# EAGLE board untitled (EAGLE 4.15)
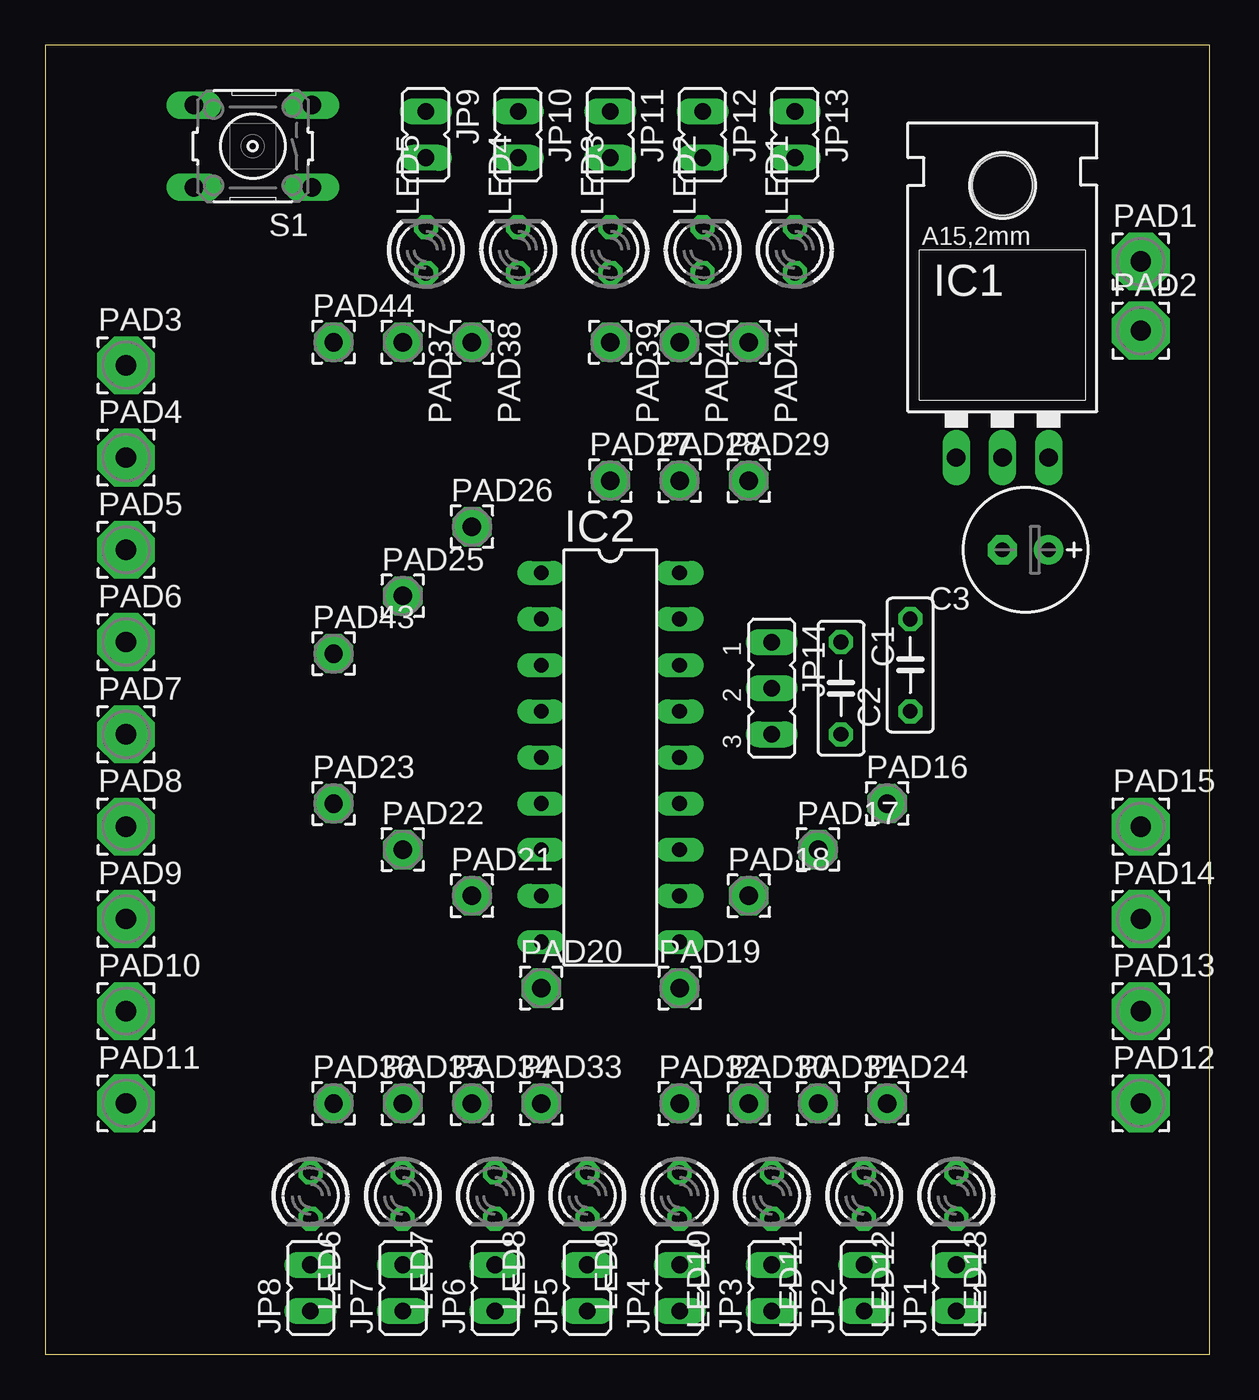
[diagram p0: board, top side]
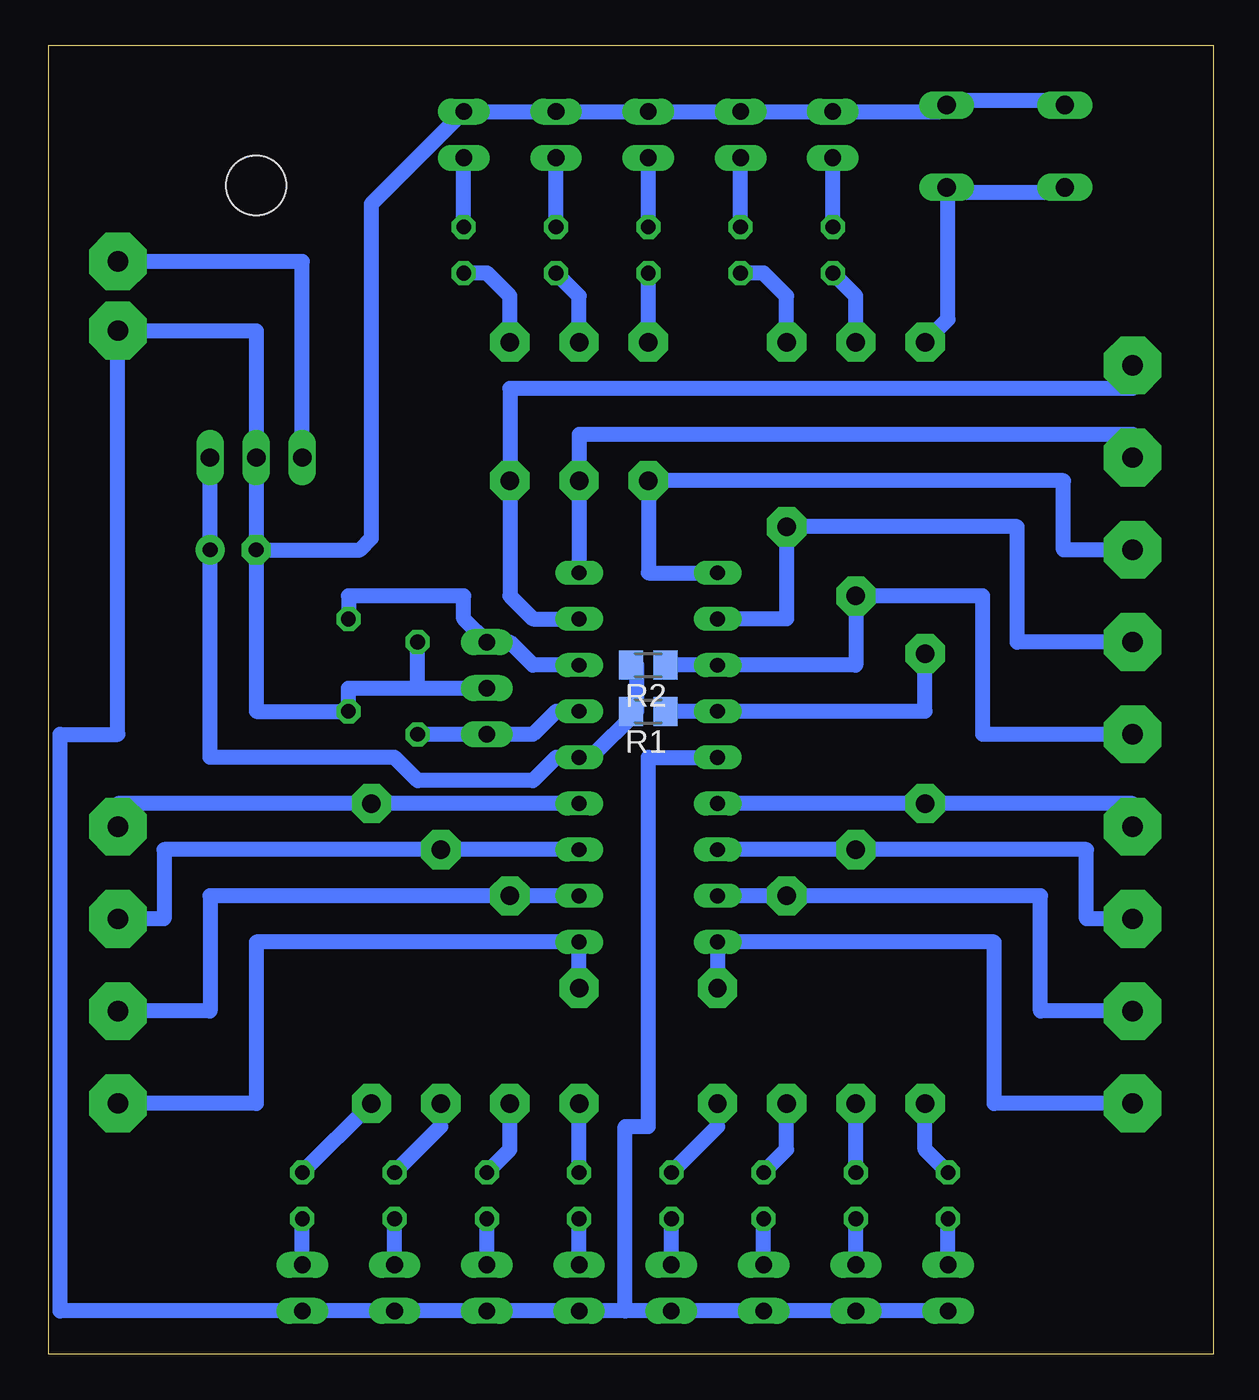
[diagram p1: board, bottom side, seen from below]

Size 64.11 x 72.06 mm. Coordinates in mm from the lower left corner, seen from the top.
Outline: 0,0 64.11,0 64.11,72.06 0,72.06 0,0
Copper layers (1*16): Top 0.035mm / dielectric 1.5mm / Bottom 0.035mm
Design rules "default": minimum track width 10mil, minimum drill 24mil, track to track 8mil, track to pad 8mil, pad to pad 8mil, via to via 8mil, smd to smd 8mil, copper to edge 40mil, drill to drill 8mil, minimum pad ring 10mil, minimum via ring 8mil, stop-mask expansion 4mil, vias tented up to drill 0mil, thermal gap 10mil

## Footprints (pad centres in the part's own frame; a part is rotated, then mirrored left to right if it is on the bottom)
C050-025X075 = drill 0.813 octagon: 1 -2.54,0; 2 2.54,0
E2,5-7 = drill 0.813 pad 1.6 round: + -1.27,0 | drill 0.813 pad 1.6 octagon: - 1.27,0
78XXL = drill 1.016 long: GND 0,-3.81; IN -2.54,-3.81; OUT 2.54,-3.81 | hole 3.302: 0,11.176
DIL18 = drill 0.813 long: 1 -10.16,-3.81; 2 -7.62,-3.81; 3 -5.08,-3.81; 4 -2.54,-3.81; 5 0,-3.81; 6 2.54,-3.81; 7 5.08,-3.81; 8 7.62,-3.81; 9 10.16,-3.81; 10 10.16,3.81; 11 7.62,3.81; 12 5.08,3.81; 13 2.54,3.81; 14 0,3.81; 15 -2.54,3.81; 16 -5.08,3.81; 17 -7.62,3.81; 18 -10.16,3.81
JP1 = drill 0.914 long: 1 0,-1.27; 2 0,1.27
JP2 = drill 0.914 long: 1 -2.54,0; 2 0,0; 3 2.54,0
LED3MM = drill 0.813 octagon: A -1.27,0; K 1.27,0
3,17/1,1 = drill 1.118 pad 3.175 octagon: 1 0,0
2,15/1,0 = drill 1.016 pad 2.159 octagon: 1 0,0
M0805 = smd 1.3 x 1.6: 1 -0.95,0; 2 0.95,0
B3F-10XX = drill 1.016 long: 1 -3.251,2.261; 2 3.251,2.261; 3 -3.251,-2.261; 4 3.251,-2.261

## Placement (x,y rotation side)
C1  [C050-025X075]  43.81,36.66 270 top
C2  [C050-025X075]  47.62,37.94 90 top
C3  [E2,5-7]  53.97,44.28 180 top
IC1  [78XXL]  52.7,53.17 0 top
IC2  PIC16F84AP  [DIL18]  31.11,32.85 270 top
JP1  [JP1]  50.16,3.64 0 top
JP2  [JP1]  45.08,3.64 0 top
JP3  [JP1]  40,3.64 0 top
JP4  [JP1]  34.92,3.64 0 top
JP5  [JP1]  29.84,3.64 0 top
JP6  [JP1]  24.76,3.64 0 top
JP7  [JP1]  19.68,3.64 0 top
JP8  [JP1]  14.6,3.64 0 top
JP9  [JP1]  20.95,67.14 180 top
JP10  [JP1]  26.03,67.14 180 top
JP11  [JP1]  31.11,67.14 180 top
JP12  [JP1]  36.19,67.14 180 top
JP13  [JP1]  41.27,67.14 180 top
JP14  [JP2]  40,36.66 270 top
LED1  [LED3MM]  41.27,60.8 90 top
LED2  [LED3MM]  36.19,60.8 90 top
LED3  [LED3MM]  31.11,60.8 90 top
LED4  [LED3MM]  26.03,60.8 90 top
LED5  [LED3MM]  20.95,60.8 90 top
LED6  [LED3MM]  14.6,8.73 270 top
LED7  [LED3MM]  19.68,8.73 270 top
LED8  [LED3MM]  24.76,8.73 270 top
LED9  [LED3MM]  29.84,8.73 270 top
LED10  [LED3MM]  34.92,8.73 270 top
LED11  [LED3MM]  40,8.73 270 top
LED12  [LED3MM]  45.08,8.73 270 top
LED13  [LED3MM]  50.16,8.73 270 top
PAD1  [3,17/1,1]  60.32,60.16 0 top
PAD2  [3,17/1,1]  60.32,56.35 0 top
PAD3  [3,17/1,1]  4.44,54.45 0 top
PAD4  [3,17/1,1]  4.44,49.37 0 top
PAD5  [3,17/1,1]  4.44,44.28 0 top
PAD6  [3,17/1,1]  4.44,39.2 0 top
PAD7  [3,17/1,1]  4.44,34.12 0 top
PAD8  [3,17/1,1]  4.44,29.04 0 top
PAD9  [3,17/1,1]  4.44,23.96 0 top
PAD10  [3,17/1,1]  4.44,18.88 0 top
PAD11  [3,17/1,1]  4.44,13.81 0 top
PAD12  [3,17/1,1]  60.32,13.81 0 top
PAD13  [3,17/1,1]  60.32,18.88 0 top
PAD14  [3,17/1,1]  60.32,23.96 0 top
PAD15  [3,17/1,1]  60.32,29.04 0 top
PAD16  [2,15/1,0]  46.35,30.31 0 top
PAD17  [2,15/1,0]  42.54,27.77 0 top
PAD18  [2,15/1,0]  38.73,25.23 0 top
PAD19  [2,15/1,0]  34.92,20.15 0 top
PAD20  [2,15/1,0]  27.3,20.15 0 top
PAD21  [2,15/1,0]  23.49,25.23 0 top
PAD22  [2,15/1,0]  19.68,27.77 0 top
PAD23  [2,15/1,0]  15.87,30.31 0 top
PAD24  [2,15/1,0]  46.35,13.81 0 top
PAD25  [2,15/1,0]  19.68,41.74 0 top
PAD26  [2,15/1,0]  23.49,45.55 0 top
PAD27  [2,15/1,0]  31.11,48.09 0 top
PAD28  [2,15/1,0]  34.92,48.09 0 top
PAD29  [2,15/1,0]  38.73,48.09 0 top
PAD30  [2,15/1,0]  38.73,13.81 0 top
PAD31  [2,15/1,0]  42.54,13.81 0 top
PAD32  [2,15/1,0]  34.92,13.81 0 top
PAD33  [2,15/1,0]  27.3,13.81 0 top
PAD34  [2,15/1,0]  23.49,13.81 0 top
PAD35  [2,15/1,0]  19.68,13.81 0 top
PAD36  [2,15/1,0]  15.87,13.81 0 top
PAD37  [2,15/1,0]  19.68,55.71 270 top
PAD38  [2,15/1,0]  23.49,55.71 270 top
PAD39  [2,15/1,0]  31.11,55.71 270 top
PAD40  [2,15/1,0]  34.92,55.71 270 top
PAD41  [2,15/1,0]  38.73,55.71 270 top
PAD43  [2,15/1,0]  15.87,38.57 0 top
PAD44  [2,15/1,0]  15.87,55.71 0 top
R1  [M0805]  31.11,35.39 180 bottom
R2  [M0805]  31.11,37.94 180 bottom
S1  [B3F-10XX]  11.43,66.51 180 top

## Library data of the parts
C1-C3 R1 R2 = rcl
IC1 = v-reg
IC2 = microchip
JP1-JP14 = jumper
LED1-LED13 = led
PAD1-PAD41 PAD43 PAD44 = wirepad
S1 = switch-omron

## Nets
GND: C1.1 C2.1 C3.- IC1.GND IC2.5 JP1.1 JP2.1 JP3.1 JP4.1 JP5.1 JP6.1 JP7.1 JP8.1 JP9.1 JP10.1 JP11.1 JP12.1 JP13.1 JP14.2 PAD2.1 S1.3 S1.4
N$1: IC1.IN PAD1.1
N$2: IC2.17 PAD3.1 PAD29.1
N$3: IC2.18 PAD4.1 PAD28.1
N$4: IC2.1 PAD5.1 PAD27.1
N$5: IC2.2 PAD6.1 PAD26.1
N$6: IC2.3 PAD7.1 PAD25.1 R2.1
N$7: IC2.6 PAD8.1 PAD23.1
N$8: IC2.7 PAD9.1 PAD22.1
N$9: IC2.8 PAD10.1 PAD21.1
N$10: IC2.9 PAD11.1 PAD20.1
N$11: IC2.10 PAD12.1 PAD19.1
N$12: IC2.11 PAD13.1 PAD18.1
N$13: IC2.12 PAD14.1 PAD17.1
N$14: IC2.13 PAD15.1 PAD16.1
N$15: C3.+ IC1.OUT IC2.14 R1.2 R2.2
N$16: IC2.4 PAD43.1 R1.1
N$17: LED13.A PAD24.1
N$18: LED11.A PAD30.1
N$19: LED9.A PAD33.1
N$20: LED7.A PAD35.1
N$21: LED5.A PAD37.1
N$22: LED3.A PAD39.1
N$23: LED1.A PAD41.1
N$24: LED12.A PAD31.1
N$25: LED10.A PAD32.1
N$26: LED8.A PAD34.1
N$27: LED6.A PAD36.1
N$28: LED4.A PAD38.1
N$29: LED2.A PAD40.1
N$30: JP1.2 LED13.K
N$31: JP2.2 LED12.K
N$32: JP3.2 LED11.K
N$33: JP4.2 LED10.K
N$34: JP5.2 LED9.K
N$35: JP6.2 LED8.K
N$36: JP7.2 LED7.K
N$37: JP8.2 LED6.K
N$38: JP9.2 LED5.K
N$39: JP10.2 LED4.K
N$40: JP11.2 LED3.K
N$41: JP12.2 LED2.K
N$42: JP13.2 LED1.K
N$43: PAD44.1 S1.1 S1.2
N$45: C2.2 IC2.16 JP14.1
N$46: C1.2 IC2.15 JP14.3

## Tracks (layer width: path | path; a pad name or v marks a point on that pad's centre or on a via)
GND
  Bottom 0.813: 43.81,36.66 JP14.2 | 43.81,36.66 C1.1 | 43.81,36.66 47.62,36.66 C2.1 52.7,35.39 C3.- | C3.- IC1.GND 52.7,56.35 PAD2.1 60.32,34.12 63.5,34.12 63.5,2.38 JP1.1 JP2.1 JP3.1 JP4.1 32.38,2.38 | JP8.1 JP7.1 JP6.1 JP5.1 32.38,2.38 | IC2.5 31.11,32.85 31.11,12.54 32.38,12.54 32.38,2.38 | S1.4 8.45,69.05 14.6,69.05 14.6,68.85 S1.3 15.03,68.41 JP9.1 JP10.1 JP11.1 JP12.1 JP13.1 46.35,63.34 46.35,44.92 46.98,44.28 C3.-
N$1
  Bottom 0.813: IC1.IN 50.16,60.16 PAD1.1
N$2
  Bottom 0.813: IC2.17 37.46,40.48 38.73,41.74 PAD29.1 38.73,53.17 4.44,53.17 PAD3.1
N$3
  Bottom 0.813: IC2.18 PAD28.1 34.92,50.63 4.44,50.63 PAD4.1
N$4
  Bottom 0.813: IC2.1 31.11,43.02 PAD27.1 8.25,48.09 8.25,44.28 PAD5.1
N$5
  Bottom 0.813: IC2.2 23.49,40.48 PAD26.1 10.79,45.55 10.79,39.2 PAD6.1
N$6
  Bottom 0.813: PAD7.1 12.7,34.12 12.7,41.74 PAD25.1 19.68,37.94 IC2.3 R2.1
N$7
  Bottom 0.813: IC2.6 PAD23.1 4.44,30.31 PAD8.1
N$8
  Bottom 0.813: IC2.7 PAD22.1 6.98,27.77 6.98,23.96 PAD9.1
N$9
  Bottom 0.813: IC2.8 PAD21.1 9.52,25.23 9.52,18.88 PAD10.1
N$10
  Bottom 0.813: IC2.9 PAD20.1 IC2.9 | IC2.9 12.06,22.7 12.06,13.81 PAD11.1
N$11
  Bottom 0.813: PAD19.1 IC2.10 52.7,22.7 52.7,13.81 PAD12.1
N$12
  Bottom 0.813: IC2.11 PAD18.1 55.24,25.23 55.24,18.88 PAD13.1
N$13
  Bottom 0.813: IC2.12 PAD17.1 57.78,27.77 57.78,23.96 PAD14.1
N$14
  Bottom 0.813: IC2.13 PAD16.1 60.32,30.31 PAD15.1
N$15
  Bottom 0.406: 31.74,37.94 R2.2
  Bottom 0.813: IC1.OUT C3.+ 55.24,32.85 45.08,32.85 43.81,31.58 37.46,31.58 36.19,32.85 IC2.14 34.29,32.85 31.74,35.39 | R1.2 31.74,35.39 | 31.74,35.39 31.74,37.94
N$16
  Bottom 0.813: PAD43.1 15.87,35.39 IC2.4 R1.1
N$17
  Bottom 0.813: LED13.A PAD24.1
N$18
  Bottom 0.813: LED11.A 38.73,11.27 PAD30.1
N$19
  Bottom 0.813: LED9.A 27.3,12.54 PAD33.1
N$20
  Bottom 0.813: LED7.A PAD35.1
N$21
  Bottom 0.813: LED5.A 19.68,58.25 PAD37.1
N$22
  Bottom 0.813: PAD39.1 LED3.A
N$23
  Bottom 0.813: LED1.A 40,59.52 38.73,58.25 PAD41.1
N$24
  Bottom 0.813: LED12.A 42.54,12.54 PAD31.1
N$25
  Bottom 0.813: LED10.A PAD32.1
N$26
  Bottom 0.813: LED8.A 23.49,11.27 PAD34.1
N$27
  Bottom 0.813: LED6.A 15.87,11.27 PAD36.1
N$28
  Bottom 0.813: LED4.A 24.76,59.52 23.49,58.25 PAD38.1
N$29
  Bottom 0.813: LED2.A 34.92,58.25 PAD40.1
N$30
  Bottom 0.813: JP1.2 LED13.K
N$31
  Bottom 0.813: JP2.2 LED12.K
N$32
  Bottom 0.813: JP3.2 LED11.K
N$33
  Bottom 0.813: JP4.2 LED10.K
N$34
  Bottom 0.813: JP5.2 LED9.K
N$35
  Bottom 0.813: JP6.2 LED8.K
N$36
  Bottom 0.813: JP7.2 LED7.K
N$37
  Bottom 0.813: JP8.2 LED6.K
N$38
  Bottom 0.813: LED5.K JP9.2
N$39
  Bottom 0.813: LED4.K JP10.2
N$40
  Bottom 0.813: LED3.K JP11.2
N$41
  Bottom 0.813: LED2.K JP12.2
N$42
  Bottom 0.813: LED1.K JP13.2
N$43
  Bottom 0.813: PAD44.1 14.6,56.98 14.6,64.17 S1.1 14.4,63.97 8.25,63.97 8.25,64.17 S1.2
N$45
  Bottom 0.813: IC2.16 37.46,37.94 38.73,39.2 JP14.1 41.27,40.48 41.27,41.74 47.62,41.74 C2.2
N$46
  Bottom 0.813: IC2.15 36.19,35.39 37.46,34.12 JP14.3 C1.2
